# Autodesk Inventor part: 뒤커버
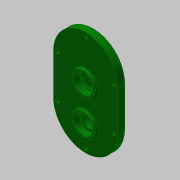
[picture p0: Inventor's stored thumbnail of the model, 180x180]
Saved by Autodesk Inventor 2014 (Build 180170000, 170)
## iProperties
Created: 2016-12
Part Number: 뒤커버
Material: 알루미늄 6061
Document SubType Name: Modeling
Designer: mduedu
Density: 2.71 g/cm^3
Mass: 236.429 g
Surface Area: 240.702 cm^2
Volume: 87.2433 cm^3
Appearance: 진녹색
Author: mduedu
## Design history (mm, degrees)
sketch "스케치1"
  geometry: L1 (40, -25)-(40, 25); L2 (-40, 25)-(-40, -25); L3 (-40, -25)-(40, 25); L4 (40, -25)-(-40, 25); A1 r 40 centre (0, 25) between (40, 25) and (-40, 25); A2 r 40 centre (0, -25) between (-40, -25) and (40, -25); 1 further point
  constraints: 8 end point, 4 point on circle, 4 tangent, 2 centre point, 2 midpoint, 1 parallel, 1 vertical
  dimensions: "d0" = 130 dimension on A2 A1; "d2" = 80 distance between parallel lines of L1 L2
extrude "돌출1" new body sketch "스케치1" distance "d3" = 10; taper "d4" = 0 deg
sketch "스케치2"
  geometry: C1 r 14 at (0, 11); 1 further point
  constraints: 1 centre point, 1 vertical alignment
  dimensions: "d5" = 28 diameter of C1; "d6" = 11 distance of C1.centre point (0, 0)
extrude "돌출2" join sketch "스케치2" distance "d7" = 3; taper "d8" = 0 deg
sketch "스케치3"
  geometry: C1 r 14 at (0, -33.1); C2 r 14 at (0, 11) reference; 1 further point
  constraints: 1 centre point, 1 vertical alignment
  dimensions: "d9" = 28 diameter of C1; "d69" = 44.1 distance of C1.centre C2.centre
extrude "돌출3" join sketch "스케치3" distance "d11" = 3; taper "d12" = 0 deg
hole "구멍1" diameter "d15" = 22; stored, may be unused: countersink angle "d19" = 90 deg, drill point angle "d21" = 0 deg; dims "d13" = 10, "d14" = 10, "d16" = 6, "d17" = 4, "d18" = 2, "d20" = 7
hole "구멍2" diameter "d24" = 18; stored, may be unused: countersink angle "d28" = 90 deg, drill point angle "d30" = 0 deg; dims "d22" = 10, "d23" = 10, "d25" = 6, "d26" = 4, "d27" = 2, "d29" = 1
hole "구멍3" diameter "d33" = 22; stored, may be unused: countersink angle "d37" = 90 deg, drill point angle "d39" = 0 deg; dims "d31" = 10, "d32" = 10, "d34" = 6, "d35" = 4, "d36" = 2, "d38" = 7
sketch "스케치4"
  geometry: C1 r 14 at (0, -33.1) reference; C2 r 18 at (0, -33.1); 1 further point
  constraints: 1 centre point, 1 coincident
  dimensions: "d40" = 36 diameter of C2
extrude "돌출4" join sketch "스케치4" distance "d41" = 4; taper "d42" = 0 deg
hole "구멍4" diameter "d45" = 22; stored, may be unused: countersink angle "d49" = 90 deg, drill point angle "d51" = 0 deg; dims "d43" = 10, "d44" = 10, "d46" = 6, "d47" = 4, "d48" = 2, "d50" = 7
hole "구멍5" diameter "d54" = 15; stored, may be unused: countersink angle "d58" = 90 deg, drill point angle "d60" = 0 deg; dims "d52" = 10, "d53" = 10, "d55" = 6, "d56" = 4, "d57" = 2, "d59" = 7
fillet "모깎기1" dims "d61" = 0.3
fillet "모깎기2" dims "d62" = 2
chamfer "모따기1" distance "d63" = 1; stored, may be unused: second distance "d64" = 2, angle "d65" = 45 deg
fillet "모깎기3" dims "d66" = 2
fillet "모깎기4" dims "d67" = 2
fillet "모깎기5" dims "d68" = 2
sketch "스케치5"
  geometry: L1 (-40, 25)-(-40, -25) reference; L2 (40, -25)-(40, 25) reference; L3 (35, 25)-(35, -25); L4 (-35, -25)-(-35, 25); A1 r 40 centre (0, 25) between (40, 25) and (-40, 25) reference; A2 r 40 centre (0, -25) between (-40, -25) and (40, -25) reference; A3 r 35 centre (0, 25) between (35, 25) and (-35, 25); A4 r 35 centre (0, -25) between (-35, -25) and (35, -25); 2 further points
  constraints: 5 point on circle, 4 end point, 2 centre point, 1 vertical alignment, 3 other
  dimensions: "d70" = 5 distance between parallel lines of L2 L3
sketch "스케치6"
  geometry: 1 further point
hole "구멍6" sketch "스케치6" at (0, 60) diameter "d71" = 4.5; stored, may be unused: countersink angle "d75" = 90 deg, drill point angle "d77" = 0 deg; dims "d72" = 6, "d73" = 8, "d74" = 4.6, "d76" = 8
node "솔리드1"
pattern_linear "직사각형 패턴1"
